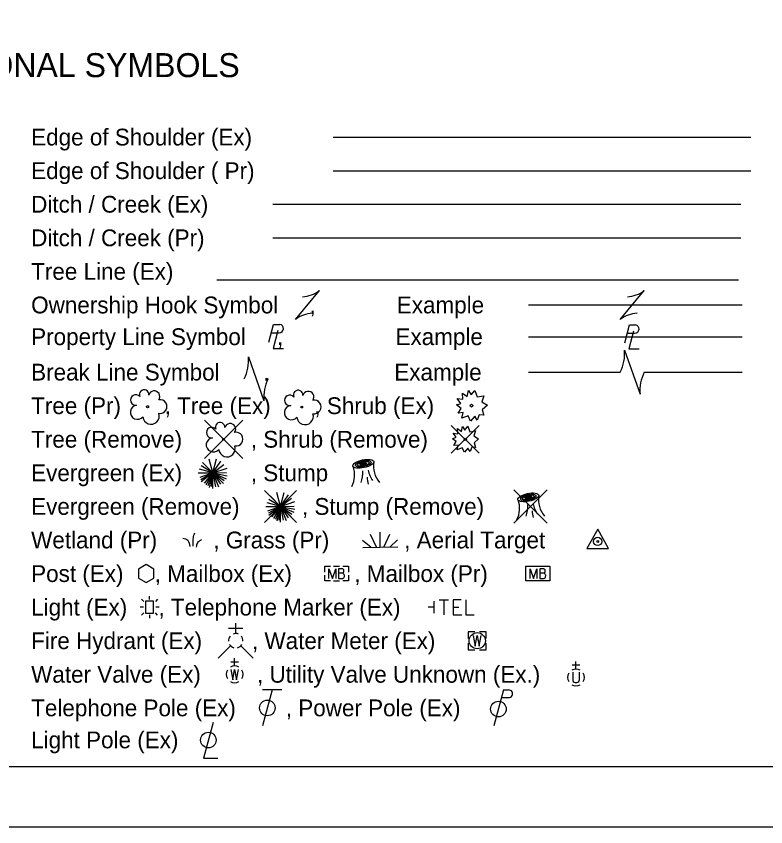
# Model space of a CAD drawing. Extents: x -1.2 to 34, y -8.5 to 22.
# Drawn here: x 7.99 to 14.24, y 0 to 6.76 of the extents above; entities that cross this region are included whole.
import ezdxf

# ---------------------------------------------------------------- set-up
doc = ezdxf.new("R2010")
doc.units = 0
for name, color, linetype in [('SH_Border', 7, 'Continuous'), ('SH_Cut_Line', 7, 'Continuous'), ('SH_Text', 7, 'Continuous')]:
    doc.layers.add(name, color=color, linetype=linetype)

msp = doc.modelspace()

# ---------------------------------------------------------------- linework, layer by layer
at = {"layer": 'SH_Border'}
msp.add_lwpolyline([(1.5, 21.5), (33.5, 21.5), (33.5, 0.5), (1.5, 0.5)], close=True, dxfattribs=at)
at = {"layer": 'SH_Cut_Line'}
msp.add_lwpolyline([(0, 0), (34, 0), (34, 22), (0, 22)], close=True, dxfattribs=at)
at = {"layer": 'SH_Text'}
for p, q in [((10.6324, 5.7516), (14.1158, 5.7516)), ((10.6324, 5.4716), (14.1158, 5.4716)), ((10.132, 5.1916), (14.032, 5.1916)), ((10.132, 4.9116), (14.032, 4.9116)), ((9.6643, 4.5616), (14.0143, 4.5616)), ((10.3193, 4.2316), (10.5193, 4.4716)), ((13.0276, 4.2316), (13.2276, 4.4716)), ((10.4193, 4.3516), (10.4193, 4.3516)), ((12.2621, 4.3516), (14.0444, 4.3516)), ((13.1276, 4.3516), (13.1276, 4.3516)), ((10.1196, 4.1206), (10.1845, 4.1206)), ((10.1597, 4.0895), (10.1597, 4.0895)), ((12.2621, 4.087), (14.0444, 4.087)), ((13.0853, 4.1165), (13.1501, 4.1165)), ((13.1253, 4.0854), (13.1253, 4.0854)), ((13.0626, 3.9758), (13.1925, 3.6076)), ((9.9269, 3.9202), (10.0569, 3.5519)), ((12.2621, 3.7916), (13.0276, 3.7916)), ((13.1276, 3.7917), (13.1276, 3.7917)), ((13.2275, 3.7916), (14.0444, 3.7916)), ((9.9919, 3.7361), (9.9919, 3.7361)), ((9.5598, 3.392), (9.8805, 3.0712)), ((9.8805, 3.392), (9.5598, 3.0712)), ((11.6189, 3.3475), (11.8506, 3.1158)), ((11.8506, 3.3475), (11.6189, 3.1158)), ((9.7201, 3.2316), (9.7201, 3.2316)), ((11.7347, 3.2317), (11.7347, 3.2317)), ((9.6306, 2.9514), (9.5997, 3.0667)), ((9.6306, 2.9514), (9.662, 3.0689)), ((9.6306, 2.9514), (9.697, 3.0485)), ((9.6306, 2.9514), (9.5203, 2.981)), ((9.6306, 2.9514), (9.5329, 3.0088)), ((9.6306, 2.9514), (9.5434, 3.0386)), ((9.6306, 2.9514), (9.722, 3.0215)), ((9.6306, 2.9514), (9.749, 2.9916)), ((9.5072, 2.9514), (9.6306, 2.9514)), ((9.6306, 2.9514), (9.5234, 2.9124)), ((9.6306, 2.9514), (9.531, 2.8944)), ((9.6306, 2.9514), (9.5329, 2.8765)), ((9.6306, 2.9514), (9.557, 2.8647)), ((9.6306, 2.9514), (9.5726, 2.851)), ((9.6306, 2.9514), (9.589, 2.8429)), ((9.6306, 2.9514), (9.599, 2.83)), ((9.6306, 2.9514), (9.6171, 2.8366)), ((9.6306, 2.9514), (9.7434, 2.9537)), ((9.6306, 2.8204), (9.6306, 2.9514)), ((9.6306, 2.9514), (9.6536, 2.8355)), ((9.6306, 2.9514), (9.6789, 2.8347)), ((9.6306, 2.9514), (9.694, 2.8566)), ((9.6306, 2.9514), (9.7203, 2.8634)), ((9.6306, 2.9514), (9.7261, 2.8875)), ((9.6306, 2.9514), (9.7422, 2.9029)), ((9.6306, 2.9514), (9.7513, 2.9275)), ((10.9043, 2.9516), (10.9043, 2.9516)), ((10.061, 2.8053), (10.3283, 2.538)), ((10.3283, 2.8053), (10.061, 2.538)), ((10.1946, 2.6716), (10.1637, 2.787)), ((10.1946, 2.6716), (10.226, 2.7891)), ((12.1408, 2.8107), (12.4189, 2.5326)), ((12.4189, 2.8107), (12.1408, 2.5326)), ((10.1946, 2.6716), (10.0969, 2.7291)), ((10.1946, 2.6716), (10.1074, 2.7588)), ((10.1946, 2.6716), (10.261, 2.7688)), ((10.1946, 2.6716), (10.286, 2.7418)), ((10.1946, 2.6716), (10.313, 2.7118)), ((10.0712, 2.6716), (10.1946, 2.6716)), ((10.1946, 2.6716), (10.0843, 2.7012)), ((10.1946, 2.6716), (10.0874, 2.6326)), ((10.1946, 2.6716), (10.095, 2.6146)), ((10.1946, 2.6716), (10.0969, 2.5968)), ((10.1946, 2.6716), (10.121, 2.585)), ((10.1946, 2.6716), (10.1367, 2.5713)), ((10.1946, 2.6716), (10.153, 2.5631)), ((10.1946, 2.6716), (10.163, 2.5502)), ((10.1946, 2.6716), (10.1811, 2.5568)), ((10.1946, 2.6716), (10.3074, 2.6739)), ((10.1946, 2.5406), (10.1946, 2.6716)), ((10.1946, 2.6716), (10.2177, 2.5557)), ((10.1946, 2.6716), (10.2429, 2.5549)), ((10.1946, 2.6716), (10.258, 2.5768)), ((10.1946, 2.6716), (10.2843, 2.5836)), ((10.1946, 2.6716), (10.2902, 2.6078)), ((10.1946, 2.6716), (10.3062, 2.6231)), ((10.1946, 2.6716), (10.3153, 2.6477)), ((10.1946, 2.6716), (10.1946, 2.6716)), ((12.2798, 2.6717), (12.2798, 2.6717)), ((12.2798, 2.6716), (12.2798, 2.6716)), ((10.9963, 2.3312), (10.9441, 2.4373)), ((11.0262, 2.3317), (11.0244, 2.4571)), ((11.0562, 2.3321), (11.1052, 2.4397)), ((10.9476, 2.3305), (10.8792, 2.3876)), ((11.105, 2.3328), (11.1715, 2.3919)), ((10.8801, 2.3295), (11.1723, 2.3338)), ((10.6374, 2.1727), (10.6875, 2.1727)), ((10.663, 2.1116), (10.663, 2.1116)), ((12.3411, 2.1116), (12.3411, 2.1116)), ((10.6374, 2.0506), (10.6875, 2.0506)), ((9.0551, 1.8801), (9.0366, 1.8988)), ((9.1033, 1.8956), (9.1033, 1.9222)), ((9.17, 1.8988), (9.1514, 1.8801)), ((9.0511, 1.832), (9.0246, 1.832)), ((9.1033, 1.8316), (9.1033, 1.8316)), ((9.1821, 1.832), (9.1554, 1.832)), ((11.476, 1.8316), (11.4262, 1.8316)), ((11.476, 1.7816), (11.476, 1.8816)), ((9.0551, 1.7832), (9.0366, 1.7645)), ((9.1033, 1.7676), (9.1033, 1.7411)), ((9.17, 1.7645), (9.1514, 1.7832)), ((9.8213, 1.6118), (9.8213, 1.6978)), ((9.8813, 1.6548), (9.7613, 1.6548)), ((9.7791, 1.5092), (9.6751, 1.4053)), ((9.8214, 1.5516), (9.8214, 1.5516)), ((9.8214, 1.5516), (9.8214, 1.5516)), ((9.8637, 1.5092), (9.9677, 1.4053)), ((11.835, 1.5516), (11.835, 1.5516)), ((9.844, 1.3735), (9.7804, 1.3735)), ((9.8123, 1.3416), (9.8123, 1.4052)), ((12.6584, 1.3153), (12.6584, 1.3788)), ((12.6902, 1.347), (12.6266, 1.347)), ((12.6313, 1.2883), (12.6313, 1.2194)), ((12.6855, 1.2883), (12.6855, 1.2194)), ((9.8123, 1.2716), (9.8123, 1.2716)), ((12.6584, 1.2453), (12.6584, 1.2453)), ((10.1253, 1.1416), (10.045, 0.8416)), ((10.2053, 1.1416), (10.0453, 1.1416)), ((12.0543, 1.1416), (11.974, 0.8416)), ((12.0543, 1.1416), (12.0968, 1.1416)), ((12.0372, 1.0779), (12.0968, 1.0779))]:
    msp.add_line(p, q, dxfattribs=at)
for points in [[(10.0986, 4.0411), (10.1377, 4.1893), (10.1894, 4.1892)], [(10.173, 4.1375), (10.1335, 3.9896), (10.2208, 3.9896)], [(13.0643, 4.037), (13.1033, 4.1852), (13.155, 4.1851)], [(13.1387, 4.1334), (13.0991, 3.9855), (13.1864, 3.9855)], [(11.7835, 3.6021), (11.8137, 3.6389), (11.8345, 3.5862), (11.889, 3.5952), (11.8721, 3.5446), (11.9194, 3.5149), (11.8765, 3.4781), (11.889, 3.4325), (11.8514, 3.4359), (11.8351, 3.3902), (11.8137, 3.4248), (11.7798, 3.384), (11.7584, 3.4283), (11.7074, 3.4068), (11.717, 3.4539), (11.6764, 3.4497), (11.7, 3.4892), (11.6616, 3.5176), (11.6985, 3.5308), (11.6682, 3.571), (11.7148, 3.5655), (11.7133, 3.6174), (11.751, 3.589), (11.7613, 3.6382), (11.7835, 3.6021)], [(11.7311, 3.3086), (11.7568, 3.3398), (11.7745, 3.295), (11.8209, 3.3027), (11.8065, 3.2597), (11.8466, 3.2344), (11.8102, 3.2032), (11.8209, 3.1643), (11.7888, 3.1672), (11.775, 3.1284), (11.7568, 3.1578), (11.728, 3.1231), (11.7098, 3.1608), (11.6664, 3.1425), (11.6746, 3.1825), (11.6401, 3.179), (11.6602, 3.2126), (11.6276, 3.2367), (11.6589, 3.2479), (11.6332, 3.2821), (11.6728, 3.2774), (11.6715, 3.3215), (11.7035, 3.2974), (11.7123, 3.3392), (11.7311, 3.3086)], [(9.0101, 2.0741), (9.075, 2.0366), (9.1399, 2.0741), (9.1399, 2.1491), (9.075, 2.1866), (9.0101, 2.1491), (9.0101, 2.0741)], [(10.563, 2.1242), (10.563, 2.1727), (10.6115, 2.1727)], [(10.7133, 2.1727), (10.763, 2.1727), (10.763, 2.1242)], [(10.6115, 2.0506), (10.563, 2.0506), (10.563, 2.0991)], [(10.5982, 2.0716), (10.5982, 2.1516), (10.6271, 2.0716), (10.6548, 2.1516), (10.6548, 2.0716)], [(10.7141, 2.1151), (10.7172, 2.1182), (10.7191, 2.1201), (10.7204, 2.122), (10.721, 2.1233), (10.7222, 2.1258), (10.7229, 2.1277), (10.7241, 2.1321), (10.7241, 2.134), (10.7241, 2.1365), (10.7235, 2.1403), (10.7222, 2.1434), (10.7204, 2.146), (10.7172, 2.1485), (10.7147, 2.1497), (10.7134, 2.1504), (10.7103, 2.1516), (10.6794, 2.1516), (10.6794, 2.0716), (10.7141, 2.0716), (10.7185, 2.0742), (10.7222, 2.0773), (10.7254, 2.0823), (10.7273, 2.088), (10.7279, 2.0937), (10.7279, 2.0975), (10.7267, 2.1012), (10.7241, 2.1069), (10.721, 2.1107), (10.7141, 2.1151), (10.6794, 2.1151)], [(10.763, 2.0991), (10.763, 2.0506), (10.7133, 2.0506)], [(12.2763, 2.0716), (12.2763, 2.1516), (12.3053, 2.0716), (12.333, 2.1516), (12.333, 2.0716)], [(12.3922, 2.1151), (12.3953, 2.1182), (12.3972, 2.1201), (12.3985, 2.122), (12.3991, 2.1233), (12.4004, 2.1258), (12.401, 2.1277), (12.4023, 2.1321), (12.4023, 2.134), (12.4023, 2.1365), (12.4016, 2.1403), (12.4004, 2.1434), (12.3985, 2.146), (12.3953, 2.1485), (12.3928, 2.1497), (12.3916, 2.1504), (12.3884, 2.1516), (12.3575, 2.1516), (12.3575, 2.0716), (12.3922, 2.0716), (12.3966, 2.0742), (12.4004, 2.0773), (12.4035, 2.0823), (12.4054, 2.088), (12.406, 2.0937), (12.406, 2.0975), (12.4048, 2.1012), (12.4023, 2.1069), (12.3991, 2.1107), (12.3922, 2.1151), (12.3575, 2.1151)], [(11.5168, 1.8937), (11.5945, 1.8937)], [(11.5561, 1.8937), (11.5561, 1.7687)], [(11.7018, 1.8937), (11.6339, 1.8937), (11.6339, 1.7687), (11.7067, 1.7687)], [(11.7412, 1.8937), (11.7412, 1.7687), (11.8091, 1.7687)], [(11.6339, 1.8317), (11.6821, 1.8317)], [(11.815, 1.6266), (11.76, 1.6266), (11.76, 1.5716)], [(11.91, 1.5716), (11.91, 1.6266), (11.855, 1.6266)], [(11.8016, 1.5966), (11.8183, 1.5066), (11.835, 1.5966), (11.8516, 1.5066), (11.8683, 1.5966)], [(11.76, 1.5316), (11.76, 1.4766), (11.815, 1.4766)], [(11.855, 1.4766), (11.91, 1.4766), (11.91, 1.5316)], [(9.7804, 1.3126), (9.7964, 1.2265), (9.8123, 1.3126), (9.8283, 1.2265), (9.8441, 1.3126)], [(9.6326, 0.8704), (9.5538, 0.5711), (9.672, 0.5711)]]:
    msp.add_lwpolyline(points, dxfattribs=at)
for points in [[(12.7493, 2.3216), (12.9293, 2.3216), (12.8393, 2.4826)], [(12.2411, 2.1727), (12.4411, 2.1727), (12.4411, 2.0506), (12.2411, 2.0506)], [(9.07, 1.7816), (9.1366, 1.7816), (9.1366, 1.8816), (9.07, 1.8816)]]:
    msp.add_lwpolyline(points, close=True, dxfattribs=at)
for centre, radius in [((11.7877, 3.5117), 0.0115), ((9.0871, 3.5035), 0.0084), ((10.3717, 3.5001), 0.0072), ((9.7201, 3.2316), 0.0072), ((11.7347, 3.2317), 0.00979), ((12.8393, 2.3795), 0.035), ((12.8393, 2.3795), 0.008), ((11.835, 1.5516), 0.0675), ((10.0851, 0.9916), 0.065), ((12.0115, 0.9816), 0.065), ((9.5932, 0.7227), 0.065)]:
    msp.add_circle(centre, radius, dxfattribs=at)
for centre, radius, start, end in [((10.3612, 4.6866), 0.2668, 273.69448, 306.33701), ((13.0694, 4.6866), 0.2668, 273.69448, 306.33701), ((10.4774, 4.0167), 0.2668, 93.69448, 126.33701), ((13.1857, 4.0167), 0.2668, 93.69448, 126.33701), ((10.1842, 4.1551), 0.0345, 270.47098, 81.3281), ((13.1498, 4.151), 0.0345, 270.47098, 81.3281), ((12.7306, 3.9434), 0.3335, 332.94224, 5.58476), ((9.5949, 3.8877), 0.3335, 332.94224, 5.58476), ((13.5245, 3.64), 0.3335, 152.94224, 185.58476), ((10.3889, 3.5844), 0.3335, 152.94224, 185.58476), ((8.9878, 3.5594), 0.0441, 39.06254, 279.54124), ((9.0576, 3.6046), 0.0395, 354.0047, 205.97412), ((9.1419, 3.5884), 0.0466, 323.82996, 165.0376), ((10.2724, 3.556), 0.0441, 39.06254, 279.54124), ((10.3422, 3.6011), 0.0395, 354.0047, 205.97412), ((10.4265, 3.5849), 0.0466, 323.82996, 165.0376), ((9.0015, 3.4571), 0.0592, 96.17219, 320.57371), ((9.1909, 3.5046), 0.0574, 259.14531, 101.45961), ((10.4755, 3.5012), 0.0574, 259.14531, 101.45961), ((9.1155, 3.4254), 0.0685, 184.94757, 19.45715), ((10.2861, 3.4536), 0.0592, 96.17219, 320.57371), ((10.4001, 3.4219), 0.0685, 184.94757, 19.45715), ((9.6208, 3.2875), 0.0441, 39.06254, 279.54124), ((9.6906, 3.3326), 0.0395, 354.0047, 205.97412), ((9.7749, 3.3165), 0.0466, 323.82996, 165.0376), ((9.8239, 3.2327), 0.0574, 259.14531, 101.45961), ((9.6345, 3.1851), 0.0592, 96.17219, 320.57371), ((9.7485, 3.1535), 0.0685, 184.94757, 19.45715), ((10.6127, 2.9343), 0.2001, 331.53375, 20.92689), ((11.1845, 3.0087), 0.2146, 171.41061, 219.91939), ((10.6284, 2.9529), 0.2527, 340.79377, 3.54808), ((11.0995, 2.9116), 0.1819, 178.79264, 197.12241), ((11.2296, 3.0545), 0.316, 194.9653, 212.12159), ((11.9883, 2.6543), 0.2001, 331.53375, 20.92689), ((12.5601, 2.7287), 0.2146, 171.41061, 219.91939), ((12.004, 2.6729), 0.2527, 340.79377, 3.54808), ((12.6052, 2.7745), 0.316, 194.9653, 212.12159), ((12.4751, 2.6316), 0.1819, 178.79264, 197.12241), ((9.8214, 1.5516), 0.06, 140.02099, 184.06293), ((9.8214, 1.5516), 0.06, 68.13946, 112.03798), ((9.8214, 1.5516), 0.06, 356.01648, 39.98885), ((9.8214, 1.5516), 0.06, 211.87877, 255.84793), ((9.8214, 1.5516), 0.06, 283.82389, 329.90967), ((9.8123, 1.2717), 0.07, 150.01836, 209.98164), ((9.8123, 1.2717), 0.07, 60.01836, 120.01574), ((9.8123, 1.2717), 0.07, 330.01836, 29.98164), ((12.6584, 1.2453), 0.07, 60.01836, 120.01574), ((12.6584, 1.2453), 0.07, 150.01836, 209.98164), ((12.6584, 1.2322), 0.03, 205.19243, 334.80757), ((12.6584, 1.2453), 0.07, 330.01836, 29.98164), ((9.8123, 1.2717), 0.07, 239.98426, 299.98164), ((12.6584, 1.2453), 0.07, 239.98426, 299.98164), ((12.0974, 1.1098), 0.0319, 268.8767, 91.1233)]:
    msp.add_arc(centre, radius, start, end, dxfattribs=at)
for centre, major_axis in [((10.8855, 3.0272), (0.0868, 0.0187)), ((10.8855, 3.0272), (0.0651, 0.0141)), ((10.8855, 3.0272), (0.0488, 0.0105)), ((10.8855, 3.0272), (0.0275, 0.0059)), ((10.8855, 3.0272), (0.0154, 0.0033)), ((12.2611, 2.7472), (0.0868, 0.0187)), ((12.2611, 2.7472), (0.0651, 0.0141)), ((12.2611, 2.7472), (0.0488, 0.0105)), ((12.2611, 2.7472), (0.0275, 0.0059)), ((12.2611, 2.7472), (0.0154, 0.0033))]:
    msp.add_ellipse(centre, major_axis=major_axis, ratio=0.36865, dxfattribs=at)
for points in [[(9.4667, 2.3402), (9.4667, 2.3875), (9.4726, 2.432), (9.4814, 2.4527)], [(9.3793, 2.4072), (9.4208, 2.3895), (9.4385, 2.3362)], [(9.4944, 2.333), (9.5063, 2.3715), (9.5358, 2.3952)]]:
    msp.add_spline(points, degree=3, dxfattribs=at)

# ---------------------------------------------------------------- texts
for s, height, p in [('CONVENTIONAL SYMBOLS', 0.2, (6.377, 6.2516)), ('Edge of Shoulder (Ex)', 0.14, (8.1158, 5.6816)), ('Edge of Shoulder ( Pr)', 0.14, (8.1158, 5.4016)), ('Ditch / Creek (Ex)', 0.14, (8.1158, 5.1216)), ('Ditch / Creek (Pr)', 0.14, (8.1158, 4.8416)), ('Tree Line (Ex)', 0.14, (8.1158, 4.5616)), ('Ownership Hook Symbol     ,             Example', 0.14, (8.1158, 4.2816)), ('Property Line Symbol     ,                  Example', 0.14, (8.1158, 4.017)), ('Break Line Symbol       ,                    Example', 0.14, (8.1158, 3.7216)), ('Tree (Pr)       , Tree (Ex)       , Shrub (Ex)', 0.14, (8.1158, 3.4416)), ('Tree (Remove)           , Shrub (Remove)', 0.14, (8.1158, 3.1616)), ('Evergreen (Ex)           , Stump ', 0.14, (8.1158, 2.8816)), ('Evergreen (Remove)          , Stump (Remove)', 0.14, (8.1158, 2.6016)), ('Wetland (Pr)         , Grass (Pr)            , Aerial Target    ', 0.14, (8.1158, 2.3216)), ('Post (Ex)     , Mailbox (Ex)          , Mailbox (Pr)', 0.14, (8.1158, 2.0416)), ('Light (Ex)     , Telephone Marker (Ex)     ', 0.14, (8.1158, 1.7616)), ('Fire Hydrant (Ex)        , Water Meter (Ex)', 0.14, (8.1158, 1.4816)), ('Water Valve (Ex)         , Utility Valve Unknown (Ex.)', 0.14, (8.1158, 1.2016)), ('Telephone Pole (Ex)        , Power Pole (Ex)', 0.14, (8.1158, 0.9216)), ('Light Pole (Ex)     ', 0.14, (8.1158, 0.6546))]:
    msp.add_text(s, height=height, dxfattribs=at).set_placement(p)

doc.saveas('drawing.dxf')
